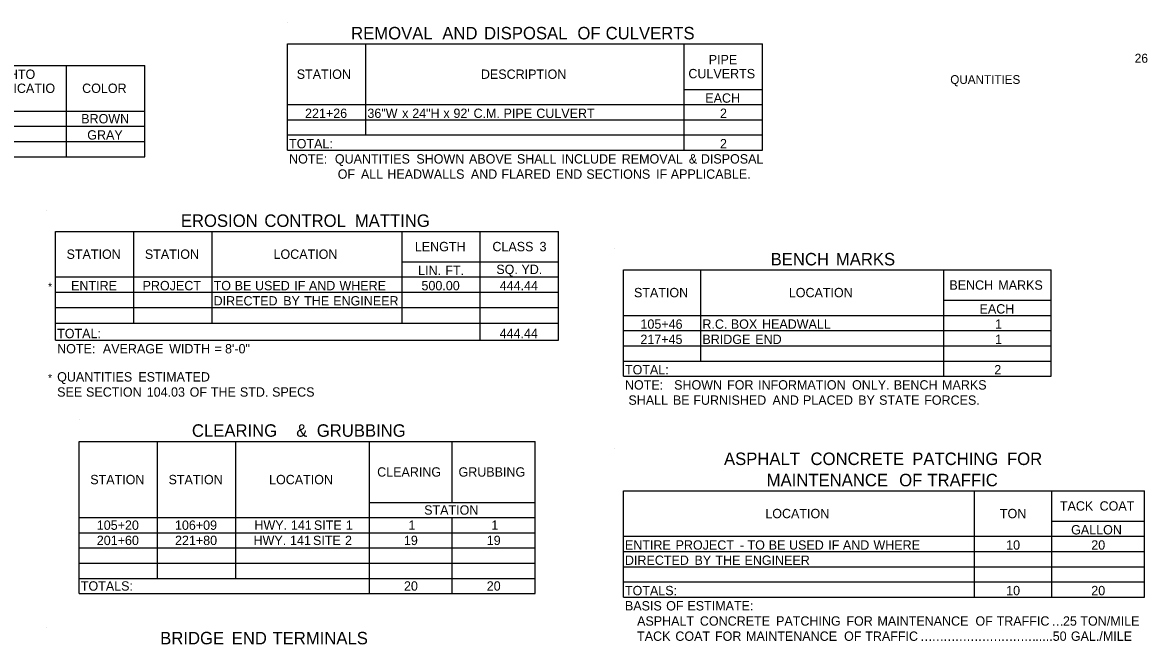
# Model space of a CAD drawing. Extents: x 1334738 to 1334853, y 402732 to 402753.
# Drawn here: x 1334792.08 to 1334810.12, y 402742.51 to 402752.48 of the extents above; entities that cross this region are included whole.
import ezdxf

# ---------------------------------------------------------------- set-up
doc = ezdxf.new("R2010")
doc.units = 0
doc.layers.add('Default', color=7, linetype='Continuous')
doc.layers.add('R_No Plot', color=7, linetype='Continuous')

msp = doc.modelspace()

# ---------------------------------------------------------------- linework, layer by layer
at = {"layer": 'Default'}
for p, q in [((1334796.328, 402752.481), (1334796.328, 402752.481)), ((1334796.328, 402752.14), (1334803.945, 402752.14)), ((1334796.328, 402750.434), (1334796.328, 402752.14)), ((1334797.583, 402750.678), (1334797.583, 402752.14)), ((1334802.69, 402750.434), (1334802.69, 402752.14)), ((1334803.945, 402750.434), (1334803.945, 402752.14)), ((1334780.108, 402751.792), (1334794.038, 402751.792)), ((1334792.783, 402750.33), (1334792.783, 402751.792)), ((1334794.038, 402750.33), (1334794.038, 402751.792)), ((1334802.69, 402751.409), (1334803.945, 402751.409)), ((1334780.108, 402751.061), (1334794.038, 402751.061)), ((1334788.42, 402751.061), (1334794.038, 402751.061)), ((1334792.783, 402750.33), (1334792.783, 402751.061)), ((1334796.328, 402751.165), (1334803.945, 402751.165)), ((1334797.583, 402750.678), (1334797.583, 402751.165)), ((1334802.69, 402750.434), (1334802.69, 402751.165)), ((1334796.328, 402750.921), (1334803.945, 402750.921)), ((1334780.108, 402750.817), (1334794.038, 402750.817)), ((1334794.038, 402750.574), (1334794.038, 402750.817)), ((1334796.328, 402750.678), (1334803.945, 402750.678)), ((1334780.108, 402750.574), (1334794.038, 402750.574)), ((1334780.108, 402750.33), (1334794.038, 402750.33)), ((1334796.328, 402750.434), (1334803.945, 402750.434)), ((1334792.46, 402749.474), (1334792.46, 402749.474)), ((1334792.606, 402749.133), (1334800.675, 402749.133)), ((1334792.606, 402747.39), (1334792.606, 402749.133)), ((1334792.606, 402747.39), (1334792.606, 402749.133)), ((1334793.862, 402747.658), (1334793.862, 402749.133)), ((1334795.117, 402747.658), (1334795.117, 402749.133)), ((1334798.164, 402747.658), (1334798.164, 402749.133)), ((1334799.419, 402747.39), (1334799.419, 402749.133)), ((1334800.675, 402747.39), (1334800.675, 402749.133)), ((1334800.675, 402747.39), (1334800.675, 402749.133)), ((1334801.569, 402748.857), (1334801.569, 402748.857)), ((1334798.164, 402748.645), (1334800.675, 402748.645)), ((1334801.715, 402748.516), (1334808.577, 402748.516)), ((1334801.715, 402746.81), (1334801.715, 402748.516)), ((1334801.715, 402746.81), (1334801.715, 402748.516)), ((1334802.958, 402747.054), (1334802.958, 402748.516)), ((1334806.858, 402746.81), (1334806.858, 402748.516)), ((1334808.577, 402746.81), (1334808.577, 402748.516)), ((1334792.606, 402748.402), (1334800.675, 402748.402)), ((1334793.862, 402747.658), (1334793.862, 402748.402)), ((1334795.117, 402747.658), (1334795.117, 402748.402)), ((1334798.164, 402747.658), (1334798.164, 402748.402)), ((1334799.419, 402747.658), (1334799.419, 402748.402)), ((1334792.606, 402748.158), (1334800.675, 402748.158)), ((1334806.858, 402748.029), (1334808.577, 402748.029)), ((1334808.577, 402746.81), (1334808.577, 402748.029)), ((1334792.606, 402747.914), (1334800.675, 402747.914)), ((1334801.715, 402747.785), (1334808.577, 402747.785)), ((1334806.858, 402746.81), (1334806.858, 402747.785)), ((1334792.606, 402747.658), (1334793.862, 402747.658)), ((1334792.606, 402747.658), (1334800.675, 402747.658)), ((1334793.862, 402747.658), (1334795.117, 402747.658)), ((1334795.117, 402747.658), (1334798.164, 402747.658)), ((1334799.419, 402747.658), (1334800.675, 402747.658)), ((1334801.715, 402747.541), (1334808.577, 402747.541)), ((1334792.606, 402747.39), (1334800.675, 402747.39)), ((1334801.715, 402747.297), (1334808.577, 402747.297)), ((1334801.715, 402747.054), (1334808.577, 402747.054)), ((1334801.715, 402746.81), (1334808.577, 402746.81)), ((1334792.986, 402746.116), (1334792.986, 402746.116)), ((1334792.986, 402745.762), (1334800.299, 402745.762)), ((1334792.986, 402743.325), (1334792.986, 402745.762)), ((1334794.242, 402743.569), (1334794.242, 402745.762)), ((1334795.497, 402743.569), (1334795.497, 402745.762)), ((1334797.642, 402743.325), (1334797.642, 402745.762)), ((1334798.97, 402744.787), (1334798.97, 402745.762)), ((1334798.97, 402744.787), (1334798.97, 402745.762)), ((1334800.299, 402743.325), (1334800.299, 402745.762)), ((1334801.569, 402745.657), (1334801.569, 402745.657)), ((1334801.715, 402744.974), (1334810.076, 402744.974)), ((1334801.715, 402743.268), (1334801.715, 402744.974)), ((1334801.715, 402743.268), (1334801.715, 402744.974)), ((1334807.346, 402743.268), (1334807.346, 402744.974)), ((1334808.589, 402743.268), (1334808.589, 402744.974)), ((1334810.076, 402743.268), (1334810.076, 402744.974)), ((1334810.076, 402744.487), (1334810.076, 402744.974)), ((1334797.642, 402744.787), (1334800.299, 402744.787)), ((1334797.642, 402744.787), (1334800.299, 402744.787)), ((1334792.986, 402744.544), (1334797.642, 402744.544)), ((1334797.642, 402744.544), (1334800.299, 402744.544)), ((1334798.97, 402743.325), (1334798.97, 402744.544)), ((1334798.97, 402743.325), (1334798.97, 402744.544)), ((1334808.589, 402744.487), (1334810.076, 402744.487)), ((1334808.589, 402743.268), (1334808.589, 402744.487)), ((1334792.986, 402744.3), (1334800.299, 402744.3)), ((1334801.715, 402744.243), (1334810.076, 402744.243)), ((1334807.346, 402743.268), (1334807.346, 402744.243)), ((1334810.076, 402743.755), (1334810.076, 402744.243)), ((1334792.986, 402744.056), (1334800.299, 402744.056)), ((1334801.715, 402743.999), (1334810.076, 402743.999)), ((1334792.986, 402743.812), (1334800.299, 402743.812)), ((1334792.986, 402743.812), (1334800.299, 402743.812)), ((1334801.715, 402743.755), (1334810.076, 402743.755)), ((1334792.986, 402743.569), (1334800.299, 402743.569)), ((1334797.642, 402743.325), (1334797.642, 402743.569)), ((1334798.97, 402743.569), (1334800.299, 402743.569)), ((1334801.715, 402743.512), (1334810.076, 402743.512)), ((1334810.076, 402743.268), (1334810.076, 402743.512)), ((1334792.986, 402743.325), (1334800.299, 402743.325)), ((1334801.715, 402743.268), (1334810.076, 402743.268)), ((1334792.46, 402742.782), (1334792.46, 402742.782))]:
    msp.add_line(p, q, dxfattribs=at)

# ---------------------------------------------------------------- texts
for s, height, p in [('REMOVAL', 0.2, (1334797.347, 402752.211)), (' AND', 0.2, (1334798.736, 402752.211)), (' DISPOSAL', 0.2, (1334799.405, 402752.211)), (' OF', 0.2, (1334800.903, 402752.211)), (' CULVERTS', 0.2, (1334801.356, 402752.211)), ('PIPE', 0.15, (1334803.084, 402751.812)), ('AASHTO', 0.15, (1334791.455, 402751.577)), ('STATION', 0.15, (1334796.475, 402751.578)), ('DESCRIPTION', 0.15, (1334799.429, 402751.578)), ('CULVERTS', 0.15, (1334802.758, 402751.587)), ('CLASSIFICATIO', 0.15, (1334791.094, 402751.352)), ('COLOR', 0.15, (1334793.032, 402751.352)), ('EACH', 0.15, (1334803.029, 402751.195)), ('221+26', 0.15, (1334796.608, 402750.951)), ('36"W', 0.15, (1334797.608, 402750.951)), (' x', 0.15, (1334798.11, 402750.951)), (' 24"H', 0.15, (1334798.272, 402750.951)), (' x', 0.15, (1334798.772, 402750.951)), (" 92'", 0.15, (1334798.933, 402750.951)), (' C.M.', 0.15, (1334799.255, 402750.951)), (' PIPE', 0.15, (1334799.737, 402750.951)), (' CULVERT', 0.15, (1334800.262, 402750.951)), ('2', 0.15, (1334803.265, 402750.951)), ('BROWN', 0.15, (1334793.017, 402750.864)), ('GRAY', 0.15, (1334793.114, 402750.604)), ('TOTAL:', 0.15, (1334796.352, 402750.464)), ('2', 0.15, (1334803.265, 402750.464)), ('NOTE:', 0.15, (1334796.352, 402750.22)), ('  QUANTITIES', 0.15, (1334796.975, 402750.22)), (' SHOWN', 0.15, (1334798.338, 402750.22)), (' ABOVE', 0.15, (1334799.182, 402750.22)), (' SHALL', 0.15, (1334799.951, 402750.22)), (' INCLUDE', 0.15, (1334800.666, 402750.22)), (' REMOVAL', 0.15, (1334801.633, 402750.22)), (' &', 0.15, (1334802.709, 402750.22)), (' DISPOSAL', 0.15, (1334802.902, 402750.22)), ('              OF', 0.15, (1334796.352, 402749.976)), (' HEADWALLS', 0.15, (1334797.872, 402749.976)), (' SECTIONS', 0.15, (1334801.065, 402749.976)), (' APPLICABLE.', 0.15, (1334802.419, 402749.976)), (' ALL', 0.15, (1334797.449, 402749.976)), (' AND', 0.15, (1334799.212, 402749.976)), (' FLARED', 0.15, (1334799.702, 402749.976)), (' END', 0.15, (1334800.576, 402749.976)), (' IF', 0.15, (1334802.184, 402749.976)), ('EROSION', 0.2, (1334794.615, 402749.204)), (' CONTROL', 0.2, (1334795.881, 402749.204)), (' MATTING', 0.2, (1334797.332, 402749.204)), ('LENGTH', 0.15, (1334798.369, 402748.814)), ('CLASS', 0.15, (1334799.614, 402748.814)), (' 3', 0.15, (1334800.314, 402748.814)), ('STATION', 0.15, (1334792.782, 402748.692)), ('STATION', 0.15, (1334794.038, 402748.692)), ('LOCATION', 0.15, (1334796.102, 402748.692)), ('BENCH', 0.2, (1334804.077, 402748.587)), (' MARKS', 0.2, (1334805.049, 402748.587)), ('LIN.', 0.15, (1334798.422, 402748.432)), (' FT.', 0.15, (1334798.803, 402748.432)), ('SQ.', 0.15, (1334799.677, 402748.449)), (' YD.', 0.15, (1334800.024, 402748.449)), ('ENTIRE', 0.15, (1334792.855, 402748.188)), ('PROJECT', 0.15, (1334794.002, 402748.188)), ('TO', 0.15, (1334795.141, 402748.188)), (' BE', 0.15, (1334795.423, 402748.188)), (' USED', 0.15, (1334795.75, 402748.188)), (' IF', 0.15, (1334796.379, 402748.188)), (' AND', 0.15, (1334796.614, 402748.188)), (' WHERE', 0.15, (1334797.104, 402748.188)), ('500.00', 0.15, (1334798.476, 402748.188)), ('444.44', 0.15, (1334799.732, 402748.188)), ('BENCH', 0.15, (1334806.945, 402748.197)), (' MARKS', 0.15, (1334807.674, 402748.197)), ('*', 0.125, (1334792.485, 402748.183)), ('STATION', 0.15, (1334801.885, 402748.076)), ('LOCATION', 0.15, (1334804.369, 402748.076)), ('DIRECTED', 0.15, (1334795.141, 402747.944)), (' BY', 0.15, (1334796.202, 402747.944)), (' THE', 0.15, (1334796.538, 402747.944)), (' ENGINEER', 0.15, (1334797.004, 402747.944)), ('EACH', 0.15, (1334807.429, 402747.815)), ('105+46', 0.15, (1334801.989, 402747.571)), ('R.C.', 0.15, (1334802.983, 402747.571)), (' BOX', 0.15, (1334803.383, 402747.571)), (' HEADWALL', 0.15, (1334803.883, 402747.571)), ('1', 0.15, (1334807.679, 402747.571)), ('TOTAL:', 0.15, (1334792.631, 402747.42)), ('444.44', 0.15, (1334799.729, 402747.42)), ('217+45', 0.15, (1334801.988, 402747.327)), ('BRIDGE', 0.15, (1334802.983, 402747.327)), (' END', 0.15, (1334803.775, 402747.327)), ('1', 0.15, (1334807.679, 402747.327)), ('NOTE:', 0.15, (1334792.631, 402747.176)), ('  AVERAGE', 0.15, (1334793.253, 402747.176)), (' WIDTH', 0.15, (1334794.372, 402747.176)), (' =', 0.15, (1334795.1, 402747.176)), (' 8\'-0"', 0.15, (1334795.269, 402747.176)), ('TOTAL:', 0.15, (1334801.74, 402746.84)), ('2', 0.15, (1334807.665, 402746.84)), ('*', 0.125, (1334792.485, 402746.72)), ('QUANTITIES', 0.15, (1334792.631, 402746.725)), (' ESTIMATED', 0.15, (1334793.878, 402746.725)), ('NOTE:', 0.15, (1334801.74, 402746.596)), ('   SHOWN', 0.15, (1334802.362, 402746.596)), (' FOR', 0.15, (1334803.323, 402746.596)), (' INFORMATION', 0.15, (1334803.82, 402746.596)), (' ONLY.', 0.15, (1334805.328, 402746.596)), (' BENCH', 0.15, (1334805.997, 402746.596)), (' MARKS', 0.15, (1334806.772, 402746.596)), ('SEE', 0.15, (1334792.631, 402746.482)), (' SECTION', 0.15, (1334793.039, 402746.482)), (' 104.03', 0.15, (1334794.012, 402746.482)), (' OF', 0.15, (1334794.701, 402746.482)), (' THE', 0.15, (1334795.041, 402746.482)), (' STD.', 0.15, (1334795.507, 402746.482)), (' SPECS', 0.15, (1334796.024, 402746.482)), (' SHALL', 0.15, (1334801.74, 402746.352)), (' BE', 0.15, (1334802.454, 402746.352)), (' FURNISHED', 0.15, (1334802.781, 402746.352)), (' AND', 0.15, (1334804.051, 402746.352)), (' PLACED', 0.15, (1334804.54, 402746.352)), (' BY', 0.15, (1334805.426, 402746.352)), (' STATE', 0.15, (1334805.762, 402746.352)), (' FORCES.', 0.15, (1334806.485, 402746.352)), ('CLEARING', 0.2, (1334794.793, 402745.839)), (' &', 0.2, (1334796.392, 402745.839)), (' GRUBBING', 0.2, (1334796.722, 402745.839)), ('ASPHALT', 0.2, (1334803.329, 402745.386)), (' CONCRETE', 0.2, (1334804.643, 402745.386)), (' PATCHING', 0.2, (1334806.275, 402745.386)), (' FOR', 0.2, (1334807.795, 402745.386)), ('CLEARING', 0.15, (1334797.765, 402745.2)), ('GRUBBING', 0.15, (1334799.07, 402745.2)), ('STATION', 0.15, (1334793.162, 402745.078)), ('STATION', 0.15, (1334794.418, 402745.078)), ('LOCATION', 0.15, (1334796.031, 402745.078)), ('MAINTENANCE', 0.2, (1334804.014, 402745.045)), (' OF', 0.2, (1334806.065, 402745.045)), (' TRAFFIC', 0.2, (1334806.518, 402745.045)), ('STATION', 0.15, (1334798.519, 402744.59)), ('TACK', 0.15, (1334808.718, 402744.655)), (' COAT', 0.15, (1334809.299, 402744.655)), ('LOCATION', 0.15, (1334803.992, 402744.533)), ('TON', 0.15, (1334807.755, 402744.533)), ('105+20', 0.15, (1334793.267, 402744.347)), ('106+09', 0.15, (1334794.521, 402744.347)), ('HWY.', 0.15, (1334795.796, 402744.347)), (' 141', 0.15, (1334796.325, 402744.347)), (' SITE', 0.15, (1334796.694, 402744.347)), (' 1', 0.15, (1334797.207, 402744.347)), ('1', 0.15, (1334798.267, 402744.347)), ('1', 0.15, (1334799.596, 402744.347)), ('GALLON', 0.15, (1334808.898, 402744.273)), ('201+60', 0.15, (1334793.267, 402744.103)), ('221+80', 0.15, (1334794.522, 402744.103)), ('HWY.', 0.15, (1334795.782, 402744.103)), (' 141', 0.15, (1334796.311, 402744.103)), (' SITE', 0.15, (1334796.68, 402744.103)), (' 2', 0.15, (1334797.193, 402744.103)), ('19', 0.15, (1334798.194, 402744.103)), ('19', 0.15, (1334799.523, 402744.103)), ('ENTIRE', 0.15, (1334801.74, 402744.029)), (' PROJECT', 0.15, (1334802.497, 402744.029)), (' TO', 0.15, (1334803.651, 402744.029)), (' BE', 0.15, (1334803.991, 402744.029)), (' USED', 0.15, (1334804.317, 402744.029)), (' IF', 0.15, (1334804.947, 402744.029)), (' AND', 0.15, (1334805.181, 402744.029)), (' WHERE', 0.15, (1334805.671, 402744.029)), ('10', 0.15, (1334807.856, 402744.029)), ('20', 0.15, (1334809.221, 402744.029)), (' -', 0.15, (1334803.529, 402744.029)), ('DIRECTED', 0.15, (1334801.74, 402743.785)), (' BY', 0.15, (1334802.8, 402743.785)), (' THE', 0.15, (1334803.136, 402743.785)), (' ENGINEER', 0.15, (1334803.602, 402743.785)), ('TOTALS:', 0.15, (1334793.011, 402743.372)), ('20', 0.15, (1334798.195, 402743.372)), ('20', 0.15, (1334799.523, 402743.372)), ('TOTALS:', 0.15, (1334801.74, 402743.298)), ('10', 0.15, (1334807.856, 402743.298)), ('20', 0.15, (1334809.221, 402743.298)), ('BASIS', 0.15, (1334801.74, 402743.054)), (' OF', 0.15, (1334802.346, 402743.054)), (' ESTIMATE:', 0.15, (1334802.686, 402743.054)), ('ASPHALT', 0.15, (1334801.935, 402742.81)), (' CONCRETE', 0.15, (1334802.886, 402742.81)), (' PATCHING', 0.15, (1334804.109, 402742.81)), (' FOR', 0.15, (1334805.237, 402742.81)), (' MAINTENANCE', 0.15, (1334805.735, 402742.81)), (' OF', 0.15, (1334807.307, 402742.81)), (' TRAFFIC', 0.15, (1334807.647, 402742.81)), ('25', 0.15, (1334808.767, 402742.81)), (' TON/MILE', 0.15, (1334808.991, 402742.81)), ('…', 0.15, (1334808.582, 402742.81)), ('BRIDGE', 0.2, (1334794.284, 402742.511)), (' END', 0.2, (1334795.357, 402742.511)), (' TERMINALS', 0.2, (1334796.011, 402742.511)), ('TACK', 0.15, (1334801.935, 402742.567)), (' COAT', 0.15, (1334802.493, 402742.567)), (' FOR', 0.15, (1334803.129, 402742.567)), (' MAINTENANCE', 0.15, (1334803.627, 402742.567)), (' OF', 0.15, (1334805.2, 402742.567)), (' TRAFFIC', 0.15, (1334805.539, 402742.567)), ('…', 0.15, (1334806.474, 402742.567)), ('…', 0.15, (1334806.659, 402742.567)), ('…', 0.15, (1334806.844, 402742.567)), ('…', 0.15, (1334807.029, 402742.567)), ('…', 0.15, (1334807.214, 402742.567)), ('…', 0.15, (1334807.399, 402742.567)), ('…', 0.15, (1334807.584, 402742.567)), ('…', 0.15, (1334807.769, 402742.567)), ('…', 0.15, (1334807.954, 402742.567)), ('…', 0.15, (1334808.139, 402742.567)), ('.....50', 0.15, (1334808.324, 402742.567)), (' GAL./MILE', 0.15, (1334808.838, 402742.567))]:
    msp.add_text(s, height=height, dxfattribs=at).set_placement(p)
at = {"layer": 'R_No Plot'}
msp.add_text('26', height=0.1444, dxfattribs=at).set_placement((1334809.917, 402751.836))
msp.add_text('QUANTITIES', height=0.14, rotation=360, dxfattribs=at).set_placement((1334806.959, 402751.497))

doc.saveas('drawing.dxf')
